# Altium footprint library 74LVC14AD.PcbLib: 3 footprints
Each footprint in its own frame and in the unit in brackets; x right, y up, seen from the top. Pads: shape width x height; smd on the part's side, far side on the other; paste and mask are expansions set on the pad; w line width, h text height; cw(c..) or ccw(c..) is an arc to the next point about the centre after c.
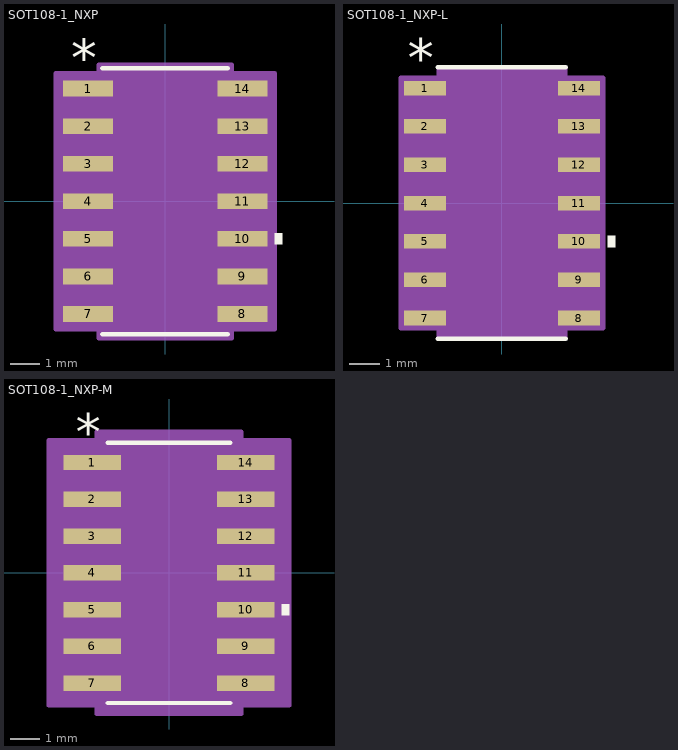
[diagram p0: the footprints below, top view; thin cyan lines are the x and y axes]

## SOT108-1_NXP [mil]
pads (14):
  rect 66.56x20.97 smd paste+0 mask+0: 1(-102.5,150) 2(-102.5,100) 3(-102.5,50) 4(-102.5,0) 5(-102.5,-50) 6(-102.5,-100) 7(-102.5,-150) 8(102.5,-150) 9(102.5,-100) 10(102.5,-50) 11(102.5,0) 12(102.5,50) 13(102.5,100) 14(102.5,150)
Top Overlay:
  region: 145.78,-42.5 155.78,-42.5 155.78,-57.5 145.78,-57.5
  lines w6: -83.5,-177 83.5,-177 ; -83.5,177 83.5,177
  text ".Designator" at -137.5,-25 h50
  text "*" at -125,165.97 h50
Mechanical 13:
  lines w1: -12,172 ccw(c0,172) 12,172 ; -122,-159.5 -122,-140.5 -78.5,-140.5 -78.5,-159.5 -122,-159.5 ; -122,-109.5 -122,-90.5 -78.5,-90.5 -78.5,-109.5 -122,-109.5 ; -122,-59.5 -122,-40.5 -78.5,-40.5 -78.5,-59.5 -122,-59.5 ; -122,-9.5 -122,9.5 -78.5,9.5 -78.5,-9.5 -122,-9.5 ; -122,40.5 -122,59.5 -78.5,59.5 -78.5,40.5 -122,40.5 ; -122,90.5 -122,109.5 -78.5,109.5 -78.5,90.5 -122,90.5 ; -122,140.5 -122,159.5 -78.5,159.5 -78.5,140.5 -122,140.5 ; -78.5,-172 78.5,-172 78.5,172 -78.5,172 -78.5,-172 ; 78.5,-159.5 78.5,-140.5 122,-140.5 122,-159.5 78.5,-159.5 ; 78.5,-109.5 78.5,-90.5 122,-90.5 122,-109.5 78.5,-109.5 ; 78.5,-59.5 78.5,-40.5 122,-40.5 122,-59.5 78.5,-59.5 ; 78.5,-9.5 78.5,9.5 122,9.5 122,-9.5 78.5,-9.5 ; 78.5,40.5 78.5,59.5 122,59.5 122,40.5 78.5,40.5 ; 78.5,90.5 78.5,109.5 122,109.5 122,90.5 78.5,90.5 ; 78.5,140.5 78.5,159.5 122,159.5 122,140.5 78.5,140.5
  text "*" at -76,119 h50
  text ".Designator" at -137.5,-25 h50
Mechanical 15:
  region: -88.5,-170.48 -145.78,-170.48 -145.78,170.48 -88.5,170.48 -88.5,182 88.5,182 88.5,170.48 145.78,170.48 145.78,-170.48 88.5,-170.48 88.5,-182 -88.5,-182
  lines w6: -145.78,-170.48 -145.78,170.48 -88.5,170.48 -88.5,182 88.5,182 88.5,170.48 145.78,170.48 145.78,-170.48 88.5,-170.48 88.5,-182 -88.5,-182 -88.5,-170.48 -145.78,-170.48
3D body "SOT108-1_NXP.step": height 69.09, standoff 0, extent -122.01,-172.01 122.01,172.01

## SOT108-1_NXP-L [mil]
pads (14):
  rect 54.75x19 smd paste+0 mask+0: 1(-100.53,150) 2(-100.53,100) 3(-100.53,50) 4(-100.53,0) 5(-100.53,-50) 6(-100.53,-100) 7(-100.53,-150) 8(100.53,-150) 9(100.53,-100) 10(100.53,-50) 11(100.53,0) 12(100.53,50) 13(100.53,100) 14(100.53,150)
Top Overlay:
  region: 137.91,-42.5 147.91,-42.5 147.91,-57.5 137.91,-57.5
  lines w6: -83.5,-177 83.5,-177 ; -83.5,177 83.5,177
  text ".Designator" at -137.5,-25 h50
  text "*" at -123.03,164 h50
Mechanical 13:
  lines w1: -12,172 ccw(c0,172) 12,172 ; -122,-159.5 -122,-140.5 -78.5,-140.5 -78.5,-159.5 -122,-159.5 ; -122,-109.5 -122,-90.5 -78.5,-90.5 -78.5,-109.5 -122,-109.5 ; -122,-59.5 -122,-40.5 -78.5,-40.5 -78.5,-59.5 -122,-59.5 ; -122,-9.5 -122,9.5 -78.5,9.5 -78.5,-9.5 -122,-9.5 ; -122,40.5 -122,59.5 -78.5,59.5 -78.5,40.5 -122,40.5 ; -122,90.5 -122,109.5 -78.5,109.5 -78.5,90.5 -122,90.5 ; -122,140.5 -122,159.5 -78.5,159.5 -78.5,140.5 -122,140.5 ; -78.5,-172 78.5,-172 78.5,172 -78.5,172 -78.5,-172 ; 78.5,-159.5 78.5,-140.5 122,-140.5 122,-159.5 78.5,-159.5 ; 78.5,-109.5 78.5,-90.5 122,-90.5 122,-109.5 78.5,-109.5 ; 78.5,-59.5 78.5,-40.5 122,-40.5 122,-59.5 78.5,-59.5 ; 78.5,-9.5 78.5,9.5 122,9.5 122,-9.5 78.5,-9.5 ; 78.5,40.5 78.5,59.5 122,59.5 122,40.5 78.5,40.5 ; 78.5,90.5 78.5,109.5 122,109.5 122,90.5 78.5,90.5 ; 78.5,140.5 78.5,159.5 122,159.5 122,140.5 78.5,140.5
  text "*" at -76,119 h50
  text ".Designator" at -137.5,-25 h50
Mechanical 15:
  region: -82.5,-163.5 -131.91,-163.5 -131.91,163.5 -82.5,163.5 -82.5,176 82.5,176 82.5,163.5 131.91,163.5 131.91,-163.5 82.5,-163.5 82.5,-176 -82.5,-176
  lines w6: -131.91,-163.5 -131.91,163.5 -82.5,163.5 -82.5,176 82.5,176 82.5,163.5 131.91,163.5 131.91,-163.5 82.5,-163.5 82.5,-176 -82.5,-176 -82.5,-163.5 -131.91,-163.5
3D body "SOT108-1_NXP.step": height 69.09, standoff 0, extent -122.01,-172.01 122.01,172.01

## SOT108-1_NXP-M [mil]
pads (14):
  rect 78.37x20.97 smd paste+0 mask+0: 1(-104.47,150) 2(-104.47,100) 3(-104.47,50) 4(-104.47,0) 5(-104.47,-50) 6(-104.47,-100) 7(-104.47,-150) 8(104.47,-150) 9(104.47,-100) 10(104.47,-50) 11(104.47,0) 12(104.47,50) 13(104.47,100) 14(104.47,150)
Top Overlay:
  region: 153.65,-42.5 163.65,-42.5 163.65,-57.5 153.65,-57.5
  lines w6: -83.5,-177 83.5,-177 ; -83.5,177 83.5,177
  text ".Designator" at -137.5,-25 h50
  text "*" at -126.97,165.97 h50
Mechanical 13:
  lines w1: -12,172 ccw(c0,172) 12,172 ; -122,-159.5 -122,-140.5 -78.5,-140.5 -78.5,-159.5 -122,-159.5 ; -122,-109.5 -122,-90.5 -78.5,-90.5 -78.5,-109.5 -122,-109.5 ; -122,-59.5 -122,-40.5 -78.5,-40.5 -78.5,-59.5 -122,-59.5 ; -122,-9.5 -122,9.5 -78.5,9.5 -78.5,-9.5 -122,-9.5 ; -122,40.5 -122,59.5 -78.5,59.5 -78.5,40.5 -122,40.5 ; -122,90.5 -122,109.5 -78.5,109.5 -78.5,90.5 -122,90.5 ; -122,140.5 -122,159.5 -78.5,159.5 -78.5,140.5 -122,140.5 ; -78.5,-172 78.5,-172 78.5,172 -78.5,172 -78.5,-172 ; 78.5,-159.5 78.5,-140.5 122,-140.5 122,-159.5 78.5,-159.5 ; 78.5,-109.5 78.5,-90.5 122,-90.5 122,-109.5 78.5,-109.5 ; 78.5,-59.5 78.5,-40.5 122,-40.5 122,-59.5 78.5,-59.5 ; 78.5,-9.5 78.5,9.5 122,9.5 122,-9.5 78.5,-9.5 ; 78.5,40.5 78.5,59.5 122,59.5 122,40.5 78.5,40.5 ; 78.5,90.5 78.5,109.5 122,109.5 122,90.5 78.5,90.5 ; 78.5,140.5 78.5,159.5 122,159.5 122,140.5 78.5,140.5
  text "*" at -76,119 h50
  text ".Designator" at -137.5,-25 h50
Mechanical 15:
  region: -98.5,-180.48 -163.65,-180.48 -163.65,180.48 -98.5,180.48 -98.5,192 98.5,192 98.5,180.48 163.65,180.48 163.65,-180.48 98.5,-180.48 98.5,-192 -98.5,-192
  lines w6: -163.65,-180.48 -163.65,180.48 -98.5,180.48 -98.5,192 98.5,192 98.5,180.48 163.65,180.48 163.65,-180.48 98.5,-180.48 98.5,-192 -98.5,-192 -98.5,-180.48 -163.65,-180.48
3D body "SOT108-1_NXP.step": height 69.09, standoff 0, extent -122.01,-172.01 122.01,172.01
